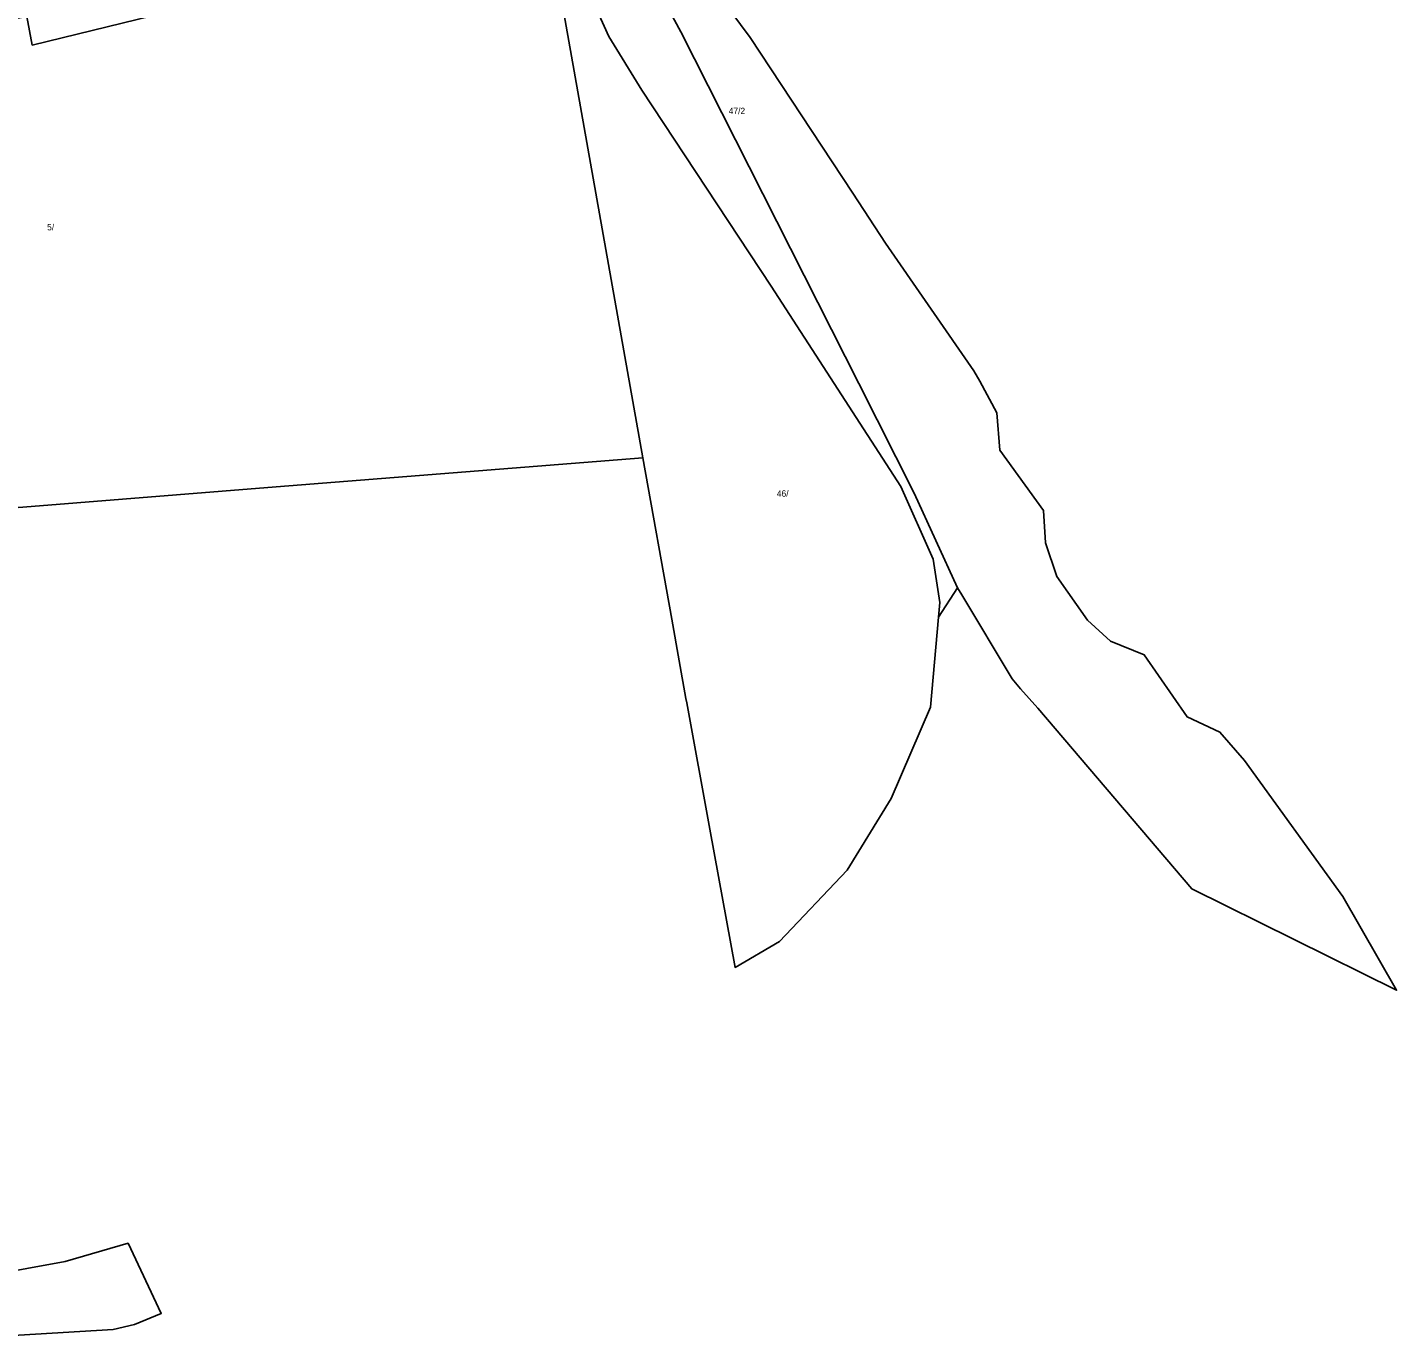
# Model space of a CAD drawing. Extents: x -793400 to -756198, y -1074141 to -1042963.
# Drawn here: x -783247 to -783084.3, y -1065508.4 to -1065351.8 of the extents above; entities that cross this region are included whole.
import ezdxf

# ---------------------------------------------------------------- set-up
doc = ezdxf.new("R2010")
doc.units = 0
for name, color, linetype in [('Parcela', 7, 'Continuous'), ('Popiskový text - Parcela', 7, 'Continuous'), ('Stavební objekt', 7, 'Continuous')]:
    doc.layers.add(name, color=color, linetype=linetype)

msp = doc.modelspace()

# ---------------------------------------------------------------- linework, layer by layer
at = {"layer": 'Parcela'}
for points in [[(-783247.38, -1065321.86), (-783242.85, -1065319.83), (-783242.12, -1065319.5), (-783224.1, -1065311.44), (-783227.89, -1065304.51), (-783235.36, -1065291.68), (-783236.57, -1065292.38), (-783237.02, -1065291.6), (-783224.24, -1065287.14), (-783221.1, -1065292.16), (-783219.72, -1065291.69), (-783214.9, -1065301.08), (-783208.77, -1065297.85), (-783206.57, -1065301.7), (-783202.15, -1065309.67), (-783189.56, -1065301.54), (-783188.2, -1065300.48), (-783187.72, -1065300.11), (-783187.81, -1065328.54), (-783185.2, -1065338.9), (-783185.97, -1065339.08), (-783246.4, -1065353.9), (-783247.05, -1065350.51)], [(-783164.64, -1065348.16), (-783161.08, -1065352.99), (-783148.91, -1065371.5), (-783145, -1065377.46), (-783134.52, -1065392.62), (-783133.79, -1065393.84), (-783131.8, -1065397.62), (-783131.42, -1065402.07), (-783126.24, -1065409.23), (-783126, -1065413.05), (-783124.67, -1065417.08), (-783121, -1065422.25), (-783118.26, -1065424.74), (-783114.26, -1065426.38), (-783109.17, -1065433.74), (-783105.27, -1065435.59), (-783102.35, -1065438.93), (-783090.68, -1065455.1), (-783084.28, -1065466.25), (-783108.62, -1065454.21), (-783126.9, -1065432.74), (-783128.96, -1065430.43), (-783129.97, -1065429.25), (-783135.94, -1065419.26), (-783136.44, -1065418.43), (-783141.62, -1065407.15), (-783148.19, -1065394.15), (-783169.31, -1065352.34), (-783175.94, -1065340.1)], [(-783251.62, -1065500.17), (-783242.49, -1065498.48), (-783235, -1065496.32), (-783231.06, -1065504.67), (-783234.23, -1065505.97), (-783236.78, -1065506.57), (-783266.48, -1065508.37)]]:
    msp.add_lwpolyline(points, dxfattribs=at)
for points in [[(-783136.44, -1065418.43), (-783138.72, -1065421.92), (-783138.56, -1065420.16), (-783139.35, -1065415.01), (-783143.17, -1065406.37), (-783158.59, -1065382.55), (-783173.97, -1065359.27), (-783177.87, -1065352.89), (-783181.79, -1065344.18), (-783184.48, -1065327.78), (-783182.62, -1065330.47), (-783175.94, -1065340.1), (-783169.31, -1065352.34), (-783148.19, -1065394.15), (-783141.62, -1065407.15)], [(-783291.97, -1065337.56), (-783284.45, -1065347.4), (-783273.57, -1065347.14), (-783271.05, -1065346.73), (-783255.53, -1065352.15), (-783254.94, -1065352.03), (-783247.05, -1065350.51), (-783246.4, -1065353.9), (-783185.97, -1065339.08), (-783185.2, -1065338.9), (-783177.15, -1065384.24), (-783173.84, -1065402.95), (-783217.4, -1065406.42), (-783247.51, -1065408.83), (-783317.57, -1065413.84), (-783316.17, -1065402.75), (-783315.7, -1065397.69), (-783318.45, -1065397.17), (-783318.2, -1065393.1), (-783318.13, -1065392.5), (-783314.55, -1065361.66), (-783301.1, -1065362.07)], [(-783157.6, -1065460.47), (-783162.89, -1065463.53), (-783165.88, -1065447.1), (-783168.63, -1065432.07), (-783168.72, -1065431.58), (-783169.51, -1065427.11), (-783170.4, -1065422.15), (-783173.84, -1065402.95), (-783177.15, -1065384.24), (-783185.2, -1065338.9), (-783181.79, -1065344.18), (-783177.87, -1065352.89), (-783173.97, -1065359.27), (-783158.59, -1065382.55), (-783143.17, -1065406.37), (-783139.35, -1065415.01), (-783138.56, -1065420.16), (-783138.72, -1065421.92), (-783139.66, -1065432.62), (-783144.33, -1065443.47), (-783149.56, -1065451.96)]]:
    msp.add_lwpolyline(points, close=True, dxfattribs=at)
at = {"layer": 'Stavební objekt'}
msp.add_lwpolyline([(-783185.97, -1065339.08), (-783246.4, -1065353.9), (-783247.05, -1065350.51), (-783249.1, -1065343.25), (-783213.13, -1065334.35), (-783188.2, -1065328.63), (-783187.81, -1065328.54), (-783185.2, -1065338.9)], close=True, dxfattribs=at)

# ---------------------------------------------------------------- texts
at = {"layer": 'Popiskový text - Parcela'}
for s, p in [('47/2', (-783163.64, -1065362.11)), ('5/', (-783244.62, -1065375.93)), ('46/', (-783157.92, -1065407.58))]:
    msp.add_text(s, height=0.75, dxfattribs=at).set_placement(p)

doc.saveas('drawing.dxf')
